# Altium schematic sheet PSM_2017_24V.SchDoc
size A4
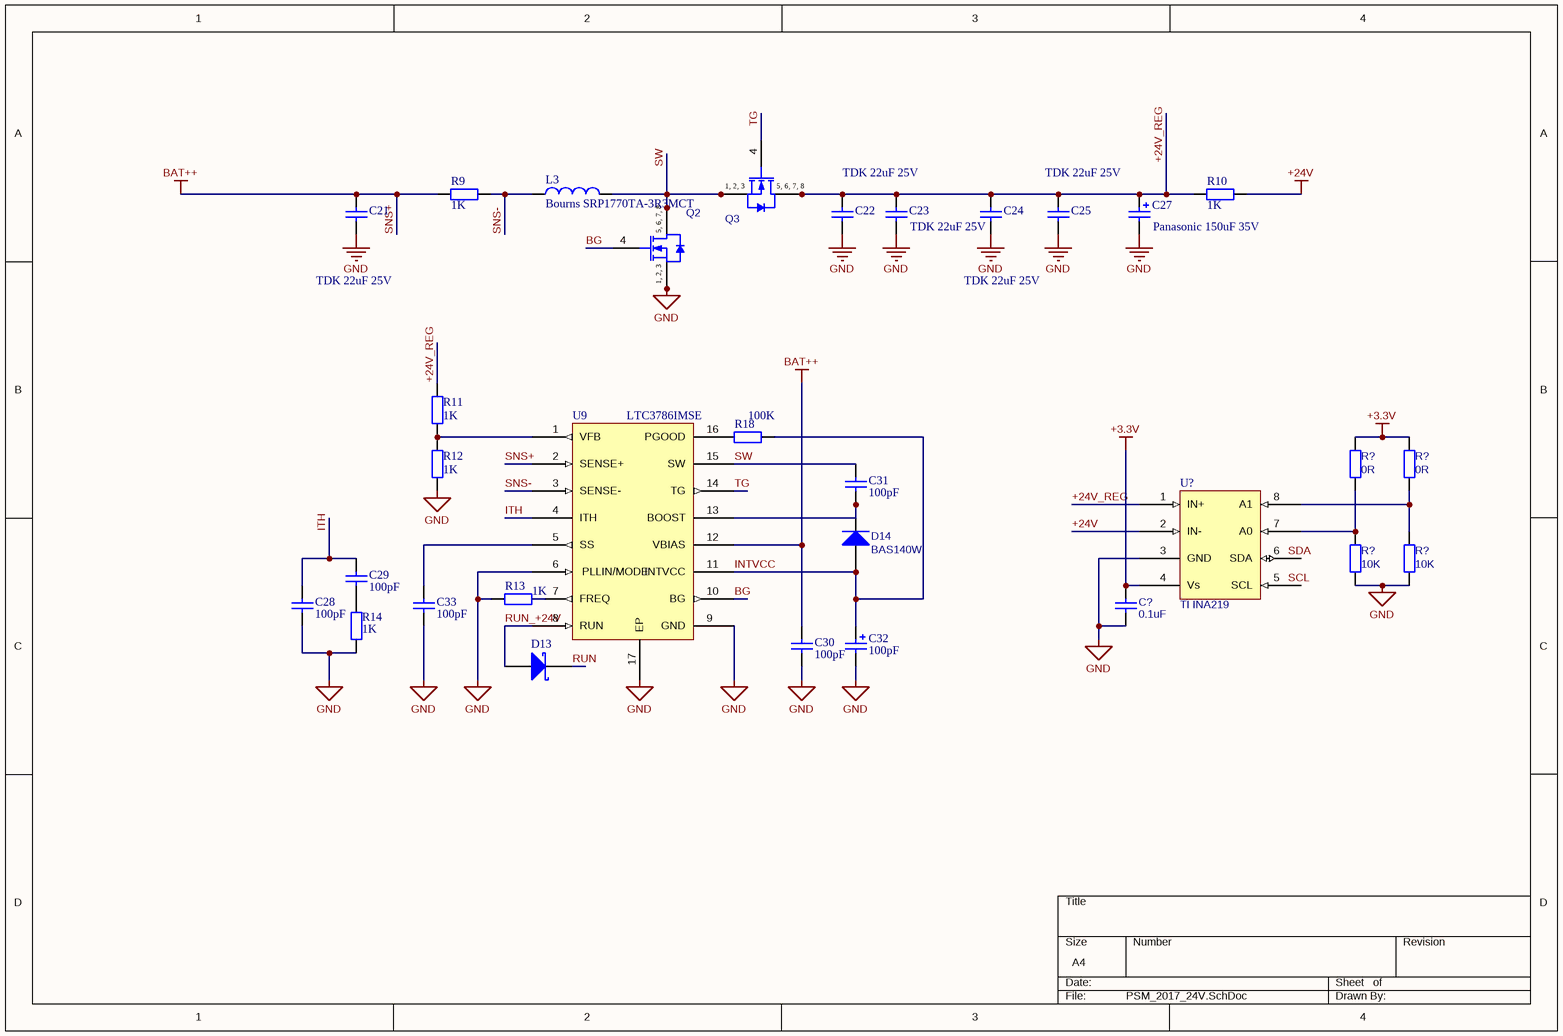
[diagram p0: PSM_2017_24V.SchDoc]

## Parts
(Parts that share a designator on the sheet are numbered #1, #2 ... from top to bottom, then left to right.)
C21  TDK 22uF 25V  [TDK C-Series 4532 (1812) SMD]
C22  TDK 22uF 25V  [TDK C-Series 4532 (1812) SMD]
C23  TDK 22uF 25V  [TDK C-Series 4532 (1812) SMD]
C24  TDK 22uF 25V  [TDK C-Series 4532 (1812) SMD]
C25  TDK 22uF 25V  [TDK C-Series 4532 (1812) SMD]
C27  Panasonic 150uF 35V  [Panasonic Capacitor, ZA-Series, F-Size]
C28  value 100pF  [C1206]  (hidden comment: Cap Semi)
C29  value 100pF  [C1206]  (hidden comment: Cap Semi)
C30  value 100pF  [C1206]  (hidden comment: Cap Semi)
C31  value 100pF  [C1206]  (hidden comment: Cap Semi)
C32  value 100pF  [POLAR0.8]  (hidden comment: Cap Pol2)
C33  value 100pF  [C1206]  (hidden comment: Cap Semi)
C?  value 0.1uF  [TDK CHIP CAP 2012(0805)]  (hidden comment: Cap Semi)
D13  ON SBD RB751S40T1G  [ON SEMI SOD-532 CASE 502]  (value not drawn)
D14  BAS140W  [INF-SOD323_V]
L3  Bourns SRP1770TA-3R3MCT  [Bourns SRP1770TA Series Inductor]
Q2  BSC027N04LS G  [INF-PG-TDSON-8-1_V]  (value not drawn)
Q3  BSC027N04LS G  [INF-PG-TDSON-8-1_V]  (value not drawn)
R9  value 1K  [AXIAL-0.4]  (hidden comment: Res2)
R10  value 1K  [AXIAL-0.4]  (hidden comment: Res2)
R11  value 1K  [AXIAL-0.4]  (hidden comment: Res2)
R12  value 1K  [AXIAL-0.4]  (hidden comment: Res2)
R13  value 1K  [AXIAL-0.4]  (hidden comment: Res2)
R14  value 1K  [AXIAL-0.4]  (hidden comment: Res2)
R18  value 100K  [AXIAL-0.4]  (hidden comment: Res2)
R?#1  value 0R  [RESC 2012 (0805) X06N]  (hidden comment: Res2)
R?#2  value 0R  [RESC 2012 (0805) X06N]  (hidden comment: Res2)
R?#3  value 10K  [RESC 2012 (0805) X06N]  (hidden comment: Res2)
R?#4  value 10K  [RESC 2012 (0805) X06N]  (hidden comment: Res2)
U9  LTC3786IMSE  [LT-MSE-16-EDP_N]
U?  TI INA219  [TI INA219 SOT-23]

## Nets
+3.3V: C?.2 R?#1.2 R?#2.2 U?.4(Vs)
+24V: R10.1 U?.2(IN-)
GND: C21.1 C22.1 C23.1 C24.1 C25.1 C27.2 C28.1 C30.1 C32.2 C33.1 C?.1 Q2.1(SOURCE) Q2.2(SOURCE) Q2.3(SOURCE) R12.1 R13.1 R14.1 R?#3.2 R?#4.2 U9.6(PLLIN/MODE) U9.9(GND) U9.17(EP) U?.3(GND)
SNS+: C21.2 C30.2 R9.2 U9.2(SENSE+) U9.12(VBIAS)  [also labelled BAT++]
+24V_REG: C22.2 C23.2 C24.2 C25.2 C27.1 Q3.5(DRAIN) Q3.6(DRAIN) Q3.7(DRAIN) Q3.8(DRAIN) R10.2 R11.2 U?.1(IN+)
BG: Q2.4(GATE) U9.10(BG)
INTVCC: C32.1 D14.2(A) R18.2 U9.11(INTVCC)
ITH: C28.2 C29.2 U9.4(ITH)
RUN: D13.1(K)
RUN_+24V: D13.2(A) U9.8(RUN)
SNS-: L3.0 R9.1 U9.3(SENSE-)
SW: C31.2 L3.1 Q2.5(DRAIN) Q2.6(DRAIN) Q2.7(DRAIN) Q2.8(DRAIN) Q3.1(SOURCE) Q3.2(SOURCE) Q3.3(SOURCE) U9.15(SW)
TG: Q3.4(GATE) U9.14(TG)
NetC29_1: C29.1 R14.2
NetC31_1: C31.1 D14.1(K) U9.13(BOOST)
NetC33_2: C33.2 U9.5(SS)
NetR11_1: R11.1 R12.2 U9.1(VFB)
NetR13_2: R13.2 U9.7(FREQ)
NetR?#1_1: R?#1.1 R?#3.1 U?.7(A0)
NetR?#2_1: R?#2.1 R?#4.1 U?.8(A1)

Not connected (* = marked no-connect by the designer): R18 1; U9 16(PGOOD); U? 5(SCL) 6(SDA)

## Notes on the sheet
- Labels drawn without touching a wire or pin: SCL, SDA

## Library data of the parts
C21-C25 = TDK 22uF 25V: TDK C4532X7R1E226M250KC, CAP CER 22UF 25V X7R 4532 (1812)
C27 = Panasonic 150uF 35V: EEHZA1V151V 150uF 35V Hyprid Cap Vibration-Proof
C28-C31 C33 C? = Cap Semi: Capacitor (Semiconductor SIM Model)
C32 = Cap Pol2: Polarized Capacitor (Axial)
D13 = ON SBD RB751S40T1G: ON Semi, 40V 30mA SBD, 0.37Vf
D14 = BAS140W: Silicon Schottky Diode, -55 to 150 degC, SOD323, Reel, Green; Manufacturer: Infineon; Configuration: Single; CT (max): 5 pF; Green: TRUE; IF (max): 120 mA; VF (max): 1,000 mV; VR (max): 40 V
L3 = Bourns SRP1770TA-3R3MCT: Bourns SRP1770TA SMD Inductor
Q2 Q3 = BSC027N04LS G: N-Channel OptiMOS 3 Power-Transistor, 40 V VDS, 100 A ID, -55 to 150 degC, PG-TDSON-8-1, Reel, Green; Manufacturer: Infineon; Green: TRUE; ID (max): 100 A; IDpuls (max): 400 A; Polarity: N; Ptot (max): 83 W; QG: 31 nC; RDS (on) (max): 2.7 mOhm; RDS (on) (max) (@4.5V): 4.1 mOhm; Rth: 1.5 K/W; RthJA (max): 50 K/W; VDS (max): 40 V; VGS(th) (max): 2 V; VGS(th) (min): 1.2 V
R9-R14 R18 R?#1-R?#4 = Res2: Resistor
U9 = LTC3786IMSE: Low IQ Synchronous Boost Controller
U? = TI INA219: Zerø-Drift, Bidirectional Current/Power Monitor With I  2C Interface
